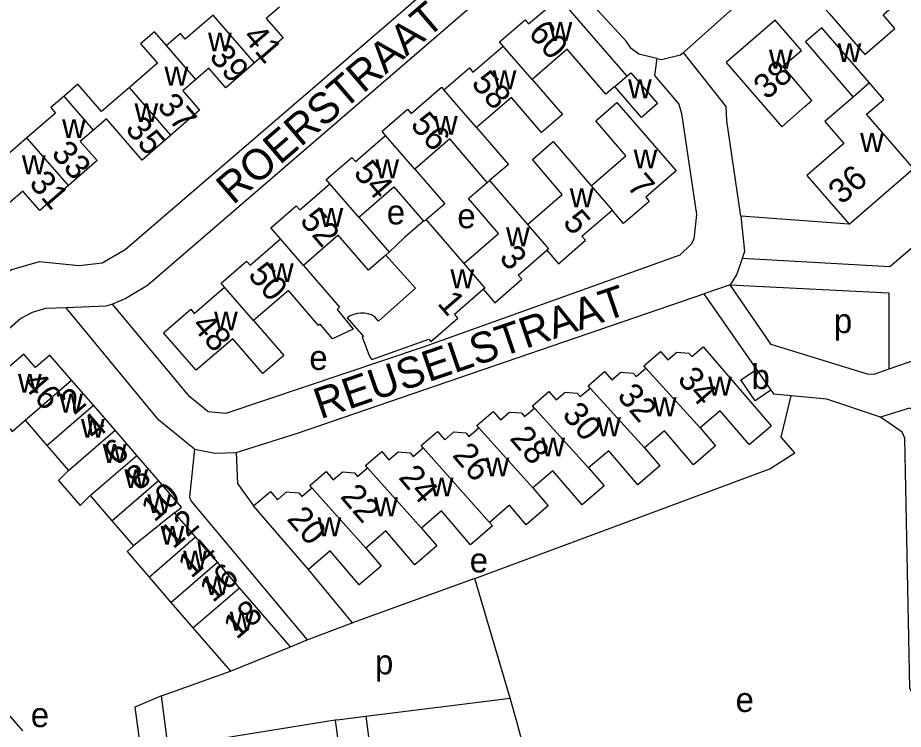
# Model space of a CAD drawing. Extents: x 156721 to 158827, y 386657 to 388950.
# Drawn here: x 157751.8 to 157896, y 387994 to 388109.8 of the extents above; entities that cross this region are included whole.
import ezdxf

# ---------------------------------------------------------------- set-up
doc = ezdxf.new("R2010")
doc.units = 0
for name, color, linetype in [('BLT_Basislijn', 7, 'Continuous'), ('BLT_Bebouwing', 7, 'Continuous'), ('BLT_Centroide', 7, 'Continuous'), ('BLT_Huisnummer', 7, 'Continuous'), ('BLT_Huisnummer_ tussenligend', 7, 'Continuous'), ('BLT_Onderverdeling_panden', 7, 'Continuous'), ('BLT_Straatnaam', 7, 'Continuous')]:
    doc.layers.add(name, color=color, linetype=linetype)

msp = doc.modelspace()

# ---------------------------------------------------------------- linework, layer by layer
at = {"layer": 'BLT_Basislijn'}
for p, q in [((157860.21, 388104.13), (157902.45, 388141.9)), ((157850.87, 388105.96), (157840.51, 388117.23)), ((157828.18, 388113.83), (157772.94, 388066.24)), ((157851.66, 388104.79), (157850.87, 388105.96)), ((157852.95, 388103.87), (157851.66, 388104.79)), ((157855.87, 388103.15), (157852.95, 388103.87)), ((157855.87, 388103.15), (157855.49, 388100.41)), ((157855.49, 388100.41), (157859.42, 388095.71)), ((157859.42, 388095.71), (157859.85, 388094.23)), ((157859.85, 388094.23), (157862.3, 388077.8)), ((157862.3, 388077.8), (157861.88, 388073.75)), ((157887.16, 388076.19), (157869.52, 388077.52)), ((157861.88, 388073.75), (157861.46, 388072.95)), ((157861.46, 388072.95), (157859.58, 388071.16)), ((157859.58, 388071.16), (157817.84, 388056.18)), ((157867.8, 388066.35), (157863.48, 388064.88)), ((157772.94, 388066.24), (157769.44, 388064.12)), ((157769.44, 388064.12), (157767.27, 388063.2)), ((157863.48, 388064.88), (157872.08, 388052.58)), ((157779.87, 388048.11), (157767.27, 388063.2)), ((157817.84, 388056.18), (157785.71, 388045.39)), ((157897.99, 388054.14), (157893.62, 388052.6)), ((157874.41, 388049.22), (157874.91, 388048.56)), ((157782.84, 388045.65), (157779.87, 388048.11)), ((157785.71, 388045.39), (157782.84, 388045.65)), ((157806.3, 388011.32), (157799.15, 388020.01)), ((157826.26, 388018.55), (157806.3, 388011.32)), ((157831.97, 387999.08), (157826.26, 388018.55)), ((157796.24, 388007.45), (157798.95, 388008.58)), ((157775.24, 387999.47), (157786.45, 388003.46)), ((157776.33, 387991.1), (157775.24, 387999.47)), ((157808.47, 387996.14), (157831.97, 387999.08)), ((157803.81, 387995.56), (157808.47, 387996.14)), ((157808.47, 387996.14), (157816.14, 387938.84)), ((157803.51, 387995.51), (157776.33, 387991.1)), ((157803.81, 387995.56), (157803.51, 387995.51)), ((157803.51, 387995.51), (157811.19, 387938.17))]:
    msp.add_line(p, q, dxfattribs=at)
for points in [[(157833.24, 388127.75), (157833.07, 388127.19), (157814.93, 388111.24), (157769.33, 388072.05), (157765.59, 388069.88), (157761.86, 388069.42), (157755.31, 388070.06), (157750.84, 388068.77), (157746.85, 388065.83), (157729.65, 388050.97)], [(157937.37, 388106.39), (157893.8, 388069.25), (157869.74, 388070.64)], [(157855.87, 388103.15), (157856.61, 388102.99), (157859.7, 388103.77), (157860.21, 388104.13)], [(157869.52, 388077.52), (157867.25, 388093), (157867.15, 388095.37), (157860.21, 388104.13)], [(157869.52, 388077.52), (157870.12, 388071.74), (157869.74, 388070.64)], [(157869.74, 388070.64), (157868.88, 388068.07), (157867.8, 388066.35)], [(157867.8, 388066.35), (157893.62, 388065.06), (157893.62, 388052.6)], [(157893.62, 388052.6), (157891.17, 388051.73), (157890.16, 388051.8), (157874.49, 388056.63), (157867.8, 388066.35)], [(157787.37, 388039.07), (157797.19, 388042.15), (157863.48, 388064.88)], [(157759.73, 388062.57), (157756.37, 388062.49), (157754.16, 388061.84), (157752.34, 388060.88), (157729.65, 388040.93)], [(157767.27, 388063.2), (157766.22, 388062.87), (157759.73, 388062.57)], [(157780.62, 388039.57), (157774.8, 388044.32), (157759.73, 388062.57)], [(157826.26, 388018.55), (157874.26, 388036.41), (157878.3, 388038.98), (157876.07, 388041.56), (157877.72, 388048.29)], [(157877.72, 388048.29), (157874.91, 388048.56)], [(157892.24, 388044.78), (157883.53, 388047.71), (157877.72, 388048.29)], [(157904.01, 387996.92), (157901.57, 388000.48), (157900.97, 388001.71), (157900.34, 388041.16), (157899.91, 388043.21), (157899.15, 388044.63), (157898.26, 388045.55), (157896.98, 388046.28), (157892.24, 388044.78)], [(157901.62, 387993.36), (157898.09, 387998.47), (157897.02, 388000.69), (157896.24, 388041.41), (157895.78, 388042.36), (157892.24, 388044.78)], [(157780.62, 388039.57), (157779.81, 388031.8), (157780.09, 388031.14), (157798.95, 388008.58)], [(157780.62, 388039.57), (157783.99, 388038.97), (157787.37, 388039.07)], [(157787.37, 388039.07), (157787.59, 388034.03), (157790.23, 388030.39)], [(157798.95, 388008.58), (157805.85, 388011.16), (157806.3, 388011.32)], [(157775.24, 387999.47), (157770.88, 387997.59), (157777.69, 387947.4)], [(157840.94, 387965.51), (157833.14, 387995.09), (157831.97, 387999.08)]]:
    msp.add_lwpolyline(points, dxfattribs=at)
at = {"layer": 'BLT_Bebouwing'}
for p, q in [((157887.16, 388076.19), (157897.65, 388085.24)), ((157828.61, 388083.32), (157834.81, 388076.13)), ((157807.33, 388077.35), (157812.28, 388071.64)), ((157818.3, 388076.89), (157824.42, 388069.78)), ((157872.08, 388052.58), (157874.41, 388049.22)), ((157764.14, 388046.74), (157760.61, 388050.83)), ((157767.68, 388042.66), (157764.14, 388046.74)), ((157753.04, 388044.29), (157756.57, 388040.21)), ((157870.89, 388040.34), (157874.48, 388043.41)), ((157771.21, 388038.57), (157767.68, 388042.66)), ((157756.57, 388040.21), (157760.11, 388036.12)), ((157774.74, 388034.49), (157771.21, 388038.57)), ((157763.64, 388032.03), (157767.17, 388027.94)), ((157799.15, 388020.01), (157790.23, 388030.39)), ((157780.76, 388025.33), (157777.37, 388029.25)), ((157767.17, 388027.94), (157770.7, 388023.86)), ((157784.34, 388021.19), (157780.76, 388025.33)), ((157787.91, 388017.05), (157784.34, 388021.19)), ((157773.2, 388018.79), (157776.77, 388014.65)), ((157796.24, 388007.45), (157787.91, 388017.05)), ((157776.77, 388014.65), (157780.35, 388010.52)), ((157780.35, 388010.52), (157786.45, 388003.46)), ((157786.45, 388003.46), (157796.24, 388007.45)), ((157749.19, 387997.71), (157752.62, 387993.75))]:
    msp.add_line(p, q, dxfattribs=at)
for points in [[(157891.89, 388117.34), (157888.62, 388121.12), (157880.65, 388114.24), (157883.92, 388110.46), (157889.69, 388103.79), (157894.62, 388108.05), (157892.69, 388110.28), (157894.97, 388112.25), (157892.13, 388115.54), (157892.89, 388116.18), (157891.89, 388117.34)], [(157830.84, 388105.19), (157830.27, 388105.86), (157834.41, 388109.47), (157834.98, 388108.8), (157839.94, 388113.06), (157850.97, 388100.29)], [(157794.43, 388111.5), (157792.29, 388109.66), (157795.04, 388106.5), (157790.37, 388102.46)], [(157783.64, 388110.23), (157779.09, 388106.3), (157778.31, 388107.21), (157776.05, 388105.26)], [(157879.96, 388095.35), (157881.11, 388096.35), (157876.37, 388101.9), (157879.41, 388104.49), (157878.39, 388105.66), (157875.09, 388109.42), (157867.12, 388102.53), (157876.18, 388092.07), (157879.96, 388095.35)], [(157890.47, 388099.18), (157882.72, 388108.13), (157880.08, 388105.85), (157887.8, 388096.87)], [(157776.05, 388105.26), (157774.09, 388107.53), (157771.82, 388105.57), (157774.57, 388102.39), (157770.02, 388098.46)], [(157821.2, 388098.04), (157825.35, 388101.62), (157825.92, 388100.96), (157830.84, 388105.19)], [(157849.01, 388098.59), (157847.58, 388097.35), (157841.24, 388104.67), (157835.55, 388099.75)], [(157790.37, 388102.46), (157785.69, 388098.41), (157782.95, 388101.58), (157780.82, 388099.74)], [(157780.82, 388099.74), (157778.69, 388097.9), (157781.43, 388094.74), (157776.76, 388090.69)], [(157835.55, 388099.75), (157840.48, 388094.06), (157837.09, 388091.13), (157832.18, 388096.81), (157826.51, 388091.91)], [(157850.97, 388100.29), (157851.62, 388100.85), (157855.96, 388095.84), (157853.35, 388093.57), (157849.01, 388098.59)], [(157770.02, 388098.46), (157765.47, 388094.53), (157761.61, 388098.98), (157759.38, 388097.06)], [(157811.72, 388090.65), (157811.15, 388091.32), (157815.3, 388094.9), (157815.88, 388094.24), (157820.81, 388098.5), (157821.2, 388098.04)], [(157897.65, 388085.24), (157890, 388094.1), (157892.78, 388096.5), (157890.47, 388099.18)], [(157759.38, 388097.06), (157757.21, 388095.18), (157757.99, 388094.27), (157753.34, 388090.25)], [(157887.8, 388096.87), (157883.2, 388092.92), (157886.29, 388089.34), (157880.26, 388084.14), (157887.16, 388076.19)], [(157845.15, 388082.47), (157850.83, 388087.35), (157845.94, 388093.03), (157849.35, 388095.99), (157859, 388084.87), (157854.04, 388080.59), (157854.62, 388079.92), (157850.45, 388076.32), (157848.57, 388078.5)], [(157776.76, 388090.69), (157772.08, 388086.64), (157766.28, 388093.35), (157764.15, 388091.51)], [(157764.15, 388091.51), (157762.02, 388089.68), (157764.75, 388086.54), (157760.09, 388082.49)], [(157826.51, 388091.91), (157831.71, 388085.91), (157828.61, 388083.32)], [(157753.34, 388090.25), (157748.81, 388086.33), (157748.02, 388087.24), (157745.76, 388085.28)], [(157802.63, 388082.78), (157802.06, 388083.45), (157806.23, 388087.05), (157806.81, 388086.39), (157811.72, 388090.65)], [(157828.25, 388083), (157822.14, 388090.09), (157816.46, 388085.18)], [(157834.81, 388076.13), (157840.46, 388081.06), (157835.6, 388086.71), (157838.96, 388089.67), (157845.15, 388082.47)], [(157816.46, 388085.18), (157821.36, 388079.53), (157818.3, 388076.89)], [(157760.09, 388082.49), (157755.42, 388078.43), (157752.67, 388081.6), (157750.54, 388079.75)], [(157794.59, 388073.82), (157793.03, 388075.62), (157797.15, 388079.19), (157797.73, 388078.53), (157802.63, 388082.78)], [(157807.33, 388077.35), (157813.04, 388082.29), (157817.89, 388076.69)], [(157824.42, 388069.78), (157830.08, 388074.7), (157825.19, 388080.36), (157828.25, 388083)], [(157837.97, 388071.96), (157839.85, 388069.77), (157844.23, 388073.59), (157843.65, 388074.26), (157848.57, 388078.5)], [(157817.89, 388076.69), (157814.81, 388074.03), (157812.28, 388071.64)], [(157785.49, 388065.95), (157784.92, 388066.62), (157789.07, 388070.21), (157789.64, 388069.55), (157794.59, 388073.82)], [(157811.75, 388071.18), (157808.9, 388068.72), (157803.99, 388074.4), (157798.32, 388069.5)], [(157811.75, 388071.18), (157816.56, 388065.79), (157810.57, 388060.42), (157809.92, 388061.18), (157809.4, 388061.45), (157808.88, 388061.62), (157808.26, 388061.74), (157807.67, 388061.75), (157807.1, 388061.69), (157806.54, 388061.53), (157805.95, 388061.27), (157805.48, 388060.97), (157808.12, 388057.94), (157807.88, 388057.85), (157808.92, 388055.1), (157809.12, 388054.62), (157809.45, 388054.21), (157818.73, 388057.52), (157819.09, 388057.1), (157823.49, 388060.89), (157822.91, 388061.57), (157827.6, 388065.61)], [(157827.6, 388065.61), (157829.47, 388063.43), (157833.86, 388067.24), (157833.28, 388067.92), (157837.97, 388071.96)], [(157798.32, 388069.5), (157804.21, 388062.68), (157803.81, 388062.33), (157806.44, 388059.14), (157803.05, 388057.55), (157801.07, 388059.96), (157800.8, 388059.73), (157795.88, 388065.42), (157790.2, 388060.51)], [(157790.2, 388060.51), (157795.13, 388054.82), (157791.73, 388051.89), (157786.83, 388057.57), (157780.88, 388052.44), (157775.58, 388058.55), (157779.99, 388062.36), (157780.57, 388061.69), (157785.49, 388065.95)], [(157854.09, 388052.79), (157853.76, 388053.17), (157856.44, 388055.48), (157857.62, 388054.12), (157859.09, 388055.39), (157861.05, 388055.23), (157861.55, 388054.66), (157863.39, 388056.27), (157874.48, 388043.41)], [(157754.73, 388052.89), (157752.84, 388055.08), (157743.6, 388047.11), (157745.82, 388044.54), (157747.72, 388046.17), (157750.92, 388042.46), (157753.04, 388044.29)], [(157760.61, 388050.83), (157757.08, 388054.91), (157754.73, 388052.89)], [(157845.01, 388049.54), (157844.69, 388049.92), (157847.36, 388052.22), (157848.54, 388050.86), (157850.02, 388052.13), (157851.98, 388051.97), (157852.48, 388051.4), (157854.09, 388052.79)], [(157874.41, 388049.22), (157871.87, 388047.47), (157869.54, 388050.86), (157872.08, 388052.58)], [(157835.95, 388046.29), (157835.63, 388046.67), (157838.3, 388048.98), (157839.47, 388047.62), (157840.95, 388048.89), (157842.91, 388048.73), (157843.4, 388048.15), (157845.01, 388049.54)], [(157826.88, 388043.04), (157826.55, 388043.42), (157829.23, 388045.72), (157830.41, 388044.36), (157831.88, 388045.63), (157833.84, 388045.48), (157834.34, 388044.9), (157835.95, 388046.29)], [(157870.89, 388040.34), (157866.17, 388045.85), (157862.9, 388043.06)], [(157817.81, 388039.79), (157817.49, 388040.17), (157820.17, 388042.47), (157821.33, 388041.12), (157822.81, 388042.39), (157824.77, 388042.23), (157825.26, 388041.65), (157826.88, 388043.04)], [(157862.9, 388043.06), (157865.41, 388040.14), (157861.83, 388037.07), (157857.1, 388042.59), (157853.83, 388039.8)], [(157808.77, 388036.54), (157808.44, 388036.92), (157811.09, 388039.22), (157812.25, 388037.87), (157813.73, 388039.14), (157815.7, 388038.98), (157816.19, 388038.4), (157817.81, 388039.79)], [(157853.83, 388039.8), (157856.34, 388036.88), (157852.75, 388033.81), (157848.02, 388039.33), (157844.76, 388036.54)], [(157760.11, 388036.12), (157758.47, 388034.51), (157762, 388030.43), (157763.64, 388032.03)], [(157799.69, 388033.29), (157799.36, 388033.67), (157802.04, 388035.97), (157803.2, 388034.62), (157804.69, 388035.89), (157806.65, 388035.73), (157807.15, 388035.15), (157808.77, 388036.54)], [(157844.76, 388036.54), (157847.26, 388033.62), (157843.68, 388030.55), (157838.95, 388036.07), (157835.69, 388033.28)], [(157777.37, 388029.25), (157778.47, 388030.18), (157774.74, 388034.49)], [(157790.23, 388030.39), (157792.95, 388032.71), (157794.12, 388031.36), (157795.6, 388032.63), (157797.57, 388032.47), (157798.07, 388031.89), (157799.69, 388033.29)], [(157835.69, 388033.28), (157838.19, 388030.36), (157834.61, 388027.29), (157831.9, 388030.46), (157828.63, 388027.66)], [(157828.63, 388027.66), (157829.12, 388027.1), (157825.54, 388024.03), (157820.81, 388029.55), (157817.55, 388026.76)], [(157817.55, 388026.76), (157820.05, 388023.84), (157816.47, 388020.77), (157811.74, 388026.29), (157808.48, 388023.49)], [(157770.7, 388023.86), (157769.62, 388022.93), (157773.2, 388018.79)], [(157808.48, 388023.49), (157810.98, 388020.57), (157807.4, 388017.5), (157802.67, 388023.03), (157799.15, 388020.01)]]:
    msp.add_lwpolyline(points, dxfattribs=at)
at = {"layer": 'BLT_Onderverdeling_panden'}
for p, q in [((157790.37, 388102.46), (157783.64, 388110.23)), ((157780.82, 388099.74), (157776.05, 388105.26)), ((157835.55, 388099.75), (157830.84, 388105.19)), ((157849.01, 388098.59), (157850.97, 388100.29)), ((157776.76, 388090.69), (157770.02, 388098.46)), ((157826.51, 388091.91), (157821.2, 388098.04)), ((157890.47, 388099.18), (157887.8, 388096.87)), ((157764.15, 388091.51), (157759.38, 388097.06)), ((157760.09, 388082.49), (157753.34, 388090.25)), ((157816.46, 388085.18), (157811.72, 388090.65)), ((157807.33, 388077.35), (157802.63, 388082.78)), ((157828.25, 388083), (157828.61, 388083.32)), ((157845.15, 388082.47), (157848.57, 388078.5)), ((157817.89, 388076.69), (157818.3, 388076.89)), ((157798.32, 388069.5), (157794.59, 388073.82)), ((157812.28, 388071.64), (157811.75, 388071.18)), ((157790.2, 388060.51), (157785.49, 388065.95)), ((157854.09, 388052.79), (157862.9, 388043.06)), ((157753.04, 388044.29), (157760.61, 388050.83)), ((157845.01, 388049.54), (157853.83, 388039.8)), ((157756.57, 388040.21), (157764.14, 388046.74)), ((157835.95, 388046.29), (157844.76, 388036.54)), ((157760.11, 388036.12), (157767.68, 388042.66)), ((157826.88, 388043.04), (157835.69, 388033.28)), ((157817.81, 388039.79), (157828.63, 388027.66)), ((157763.64, 388032.03), (157771.21, 388038.57)), ((157808.77, 388036.54), (157817.55, 388026.76)), ((157767.17, 388027.94), (157774.74, 388034.49)), ((157799.69, 388033.29), (157808.48, 388023.49)), ((157777.37, 388029.25), (157770.7, 388023.86)), ((157773.2, 388018.79), (157780.76, 388025.33)), ((157776.77, 388014.65), (157784.34, 388021.19)), ((157780.35, 388010.52), (157787.91, 388017.05))]:
    msp.add_line(p, q, dxfattribs=at)
for points in [[(157834.81, 388076.13), (157838.21, 388072.17), (157837.97, 388071.96)], [(157824.42, 388069.78), (157827.84, 388065.81), (157827.6, 388065.61)]]:
    msp.add_lwpolyline(points, dxfattribs=at)

# ---------------------------------------------------------------- texts
at = {"layer": 'BLT_Centroide'}
for s, p in [('w', (157838.23, 388106.03)), ('w', (157782.8, 388104.31)), ('w', (157885.28, 388102.57)), ('w', (157874.11, 388101.52)), ('w', (157775.72, 388098.75)), ('w', (157829.14, 388098.16)), ('w', (157851.17, 388096.69)), ('w', (157770.84, 388092.81)), ('w', (157819.58, 388090.75)), ('w', (157759.05, 388090.22)), ('w', (157888.94, 388087.97)), ('w', (157852.08, 388085.28)), ('w', (157752.52, 388084.34)), ('w', (157810.04, 388083.69)), ('w', (157841.69, 388078.94)), ('e', (157811.9, 388076.17)), ('w', (157800.95, 388075.75)), ('e', (157823.39, 388075.55)), ('w', (157831.31, 388072.61)), ('w', (157792.89, 388066.78)), ('w', (157822.26, 388065.78)), ('w', (157783.79, 388058.91)), ('p', (157884.68, 388058.47)), ('e', (157799.3, 388052.49)), ('b', (157871.27, 388049.39)), ('w', (157751.87, 388048.78)), ('w', (157864.21, 388048.31)), ('w', (157758.59, 388045.53)), ('w', (157855.2, 388044.94)), ('w', (157846.13, 388041.69)), ('w', (157762.12, 388041.44)), ('w', (157765.66, 388037.34)), ('w', (157837.05, 388038.41)), ('w', (157827.98, 388035.16)), ('w', (157769.19, 388033.25)), ('w', (157818.91, 388031.91)), ('w', (157772.94, 388029.19)), ('w', (157809.84, 388028.66)), ('w', (157800.64, 388025.41)), ('w', (157775.08, 388024.03)), ('w', (157778.77, 388020)), ('e', (157825.4, 388019.53)), ('w', (157782.34, 388015.84)), ('w', (157786.34, 388010.06)), ('p', (157809.99, 388002.96)), ('e', (157868.68, 387996.83)), ('e', (157753.96, 387994.37))]:
    msp.add_text(s, height=4, dxfattribs=at).set_placement(p)
at = {"layer": 'BLT_Huisnummer'}
for s, rotation, p in [('60', 310.9394, (157834.78, 388107.2)), ('39', 310.8242, (157782.86, 388103.38)), ('38', 40.9617, (157873.76, 388096.32)), ('56', 310.9394, (157815.6, 388092.31)), ('35', 310.8242, (157769.19, 388091.62)), ('33', 310.7458, (157757.15, 388087.64)), ('36', 40.7726, (157885.93, 388079.26)), ('7', 310.7112, (157850.83, 388082.32)), ('52', 310.9394, (157797.6, 388076.69)), ('1', 310.8394, (157820, 388063.25)), ('48', 310.9394, (157780, 388059.62)), ('34', 310.6739, (157859.05, 388050.88)), ('46', 310.8312, (157752.4, 388050.16)), ('2', 40.8255, (157761.01, 388045.02)), ('28', 310.6739, (157831.77, 388041.29)), ('6', 40.8255, (157767.98, 388036.76)), ('24', 310.6739, (157813.68, 388034.93)), ('10', 40.8255, (157774.07, 388027.62)), ('20', 310.6739, (157795.49, 388028.18)), ('14', 40.8255, (157780.08, 388018.46)), ('18', 40.8255, (157787.47, 388008.51))]:
    msp.add_text(s, height=4, rotation=rotation, dxfattribs=at).set_placement(p)
at = {"layer": 'BLT_Huisnummer_ tussenligend'}
for s, rotation, p in [('41', 310.8242, (157788.3, 388106.58)), ('58', 310.9394, (157825.51, 388099.05)), ('37', 310.8242, (157774.36, 388095.4)), ('54', 310.9394, (157806.33, 388084.46)), ('31', 310.7458, (157753.53, 388082.79)), ('5', 310.8394, (157840.4, 388076.42)), ('3', 310.8394, (157830.05, 388070.66)), ('50', 310.9394, (157789.16, 388067.86)), ('32', 310.6739, (157849.25, 388048.18)), ('30', 310.6739, (157840.3, 388045.13)), ('4', 40.8255, (157764.41, 388040.89)), ('26', 310.6739, (157822.43, 388038.54)), ('8', 40.8255, (157771.59, 388032.66)), ('22', 310.6739, (157804.2, 388031.82)), ('12', 40.8255, (157777.14, 388023.22)), ('16', 40.8255, (157783.59, 388014.5))]:
    msp.add_text(s, height=4, rotation=rotation, dxfattribs=at).set_placement(p)
at = {"layer": 'BLT_Straatnaam'}
for s, rotation, p in [('ROERSTRAAT', 40.6125, (157786.88, 388079.23)), ('REUSELSTRAAT', 18.9316, (157801.1, 388044.45))]:
    msp.add_text(s, height=5, rotation=rotation, dxfattribs=at).set_placement(p)

doc.saveas('drawing.dxf')
